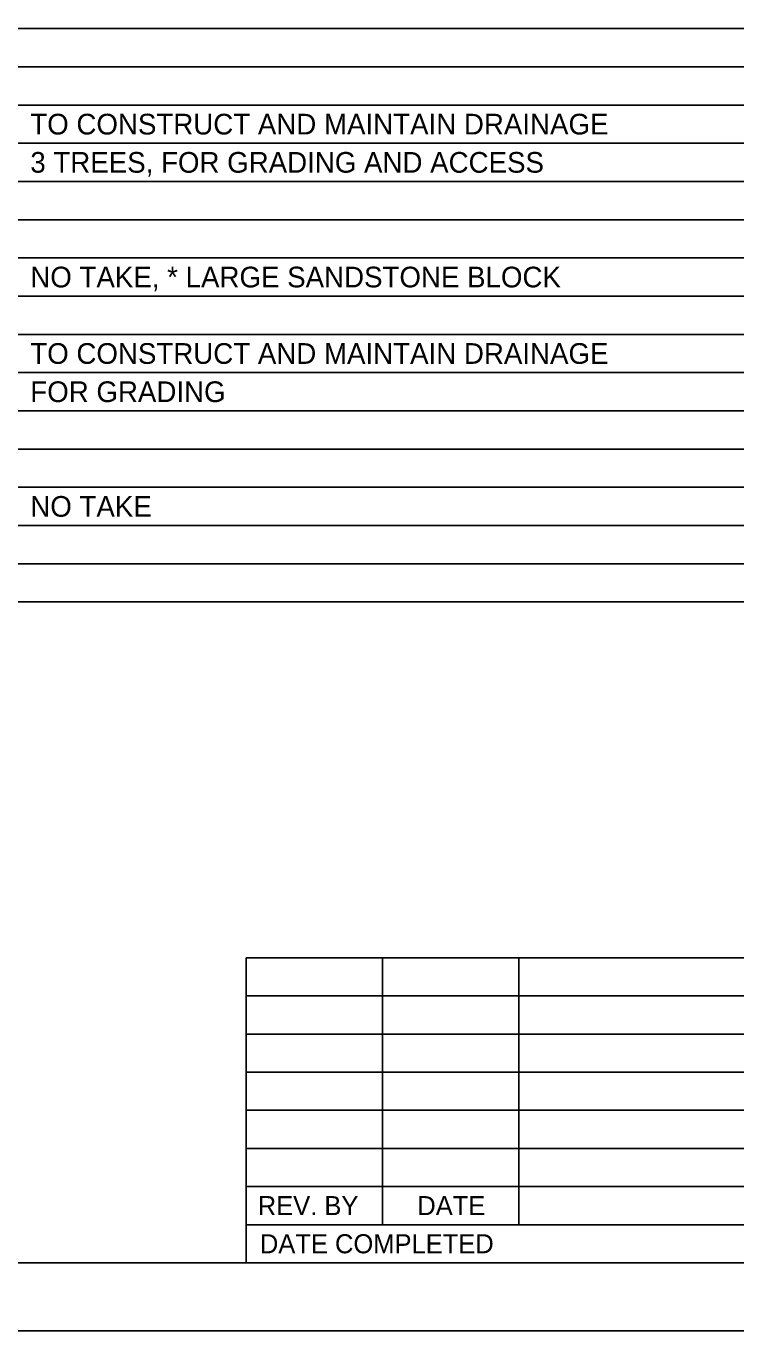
# Model space of a CAD drawing. Extents: x 0 to 34, y 0 to 22.
# Drawn here: x 23.58 to 28.79, y 0 to 9.58 of the extents above; entities that cross this region are included whole.
import ezdxf

# ---------------------------------------------------------------- set-up
doc = ezdxf.new("R2010")
doc.units = 0
for name, color, linetype in [('SH_Border', 7, 'Continuous'), ('SH_Cut_Line', 7, 'Continuous'), ('SH_Text', 7, 'Continuous')]:
    doc.layers.add(name, color=color, linetype=linetype)

msp = doc.modelspace()

# ---------------------------------------------------------------- linework, layer by layer
at = {"layer": 'SH_Border'}
msp.add_lwpolyline([(1.5, 21.5), (33.5, 21.5), (33.5, 0.5), (1.5, 0.5)], close=True, dxfattribs=at)
at = {"layer": 'SH_Cut_Line'}
msp.add_lwpolyline([(0, 0), (34, 0), (34, 22), (0, 22)], close=True, dxfattribs=at)
at = {"layer": 'SH_Text'}
for p, q in [((1.5, 9.5636), (32, 9.5636)), ((1.5, 9.2829), (32, 9.2829)), ((1.5, 9.0022), (32, 9.0022)), ((1.5, 8.7214), (32, 8.7214)), ((1.5, 8.4407), (32, 8.4407)), ((1.5, 8.16), (32, 8.16)), ((1.5, 7.8793), (32, 7.8793)), ((1.5, 7.5985), (32, 7.5985)), ((1.5, 7.3178), (32, 7.3178)), ((1.5, 7.0371), (32, 7.0371)), ((1.5, 6.7564), (32, 6.7564)), ((1.5, 6.4756), (32, 6.4756)), ((1.5, 6.1949), (32, 6.1949)), ((1.5, 5.9142), (32, 5.9142)), ((1.5, 5.6335), (32, 5.6335)), ((32, 5.3527), (1.5, 5.3527)), ((1.5, 5.3527), (32, 5.3527)), ((25.1966, 2.74), (25.1966, 0.5)), ((25.1966, 2.74), (32, 2.74)), ((26.1966, 2.74), (26.1966, 0.78)), ((27.1966, 2.74), (27.1966, 0.78)), ((25.1966, 2.46), (32, 2.46)), ((25.1966, 2.18), (32, 2.18)), ((25.1966, 1.9), (32, 1.9)), ((25.1966, 1.62), (32, 1.62)), ((25.1966, 1.34), (32, 1.34)), ((25.1966, 1.06), (32, 1.06)), ((25.1966, 0.78), (32, 0.78))]:
    msp.add_line(p, q, dxfattribs=at)

# ---------------------------------------------------------------- texts
for s, height, p in [('TO CONSTRUCT AND MAINTAIN DRAINAGE', 0.151922, (23.6113, 8.7858)), ('3 TREES, FOR GRADING AND ACCESS', 0.151922, (23.6113, 8.5051)), ('NO TAKE, * LARGE SANDSTONE BLOCK', 0.151922, (23.6113, 7.6629)), ('TO CONSTRUCT AND MAINTAIN DRAINAGE', 0.151922, (23.6113, 7.1015)), ('FOR GRADING', 0.151922, (23.6113, 6.8208)), ('NO TAKE', 0.15192, (23.6113, 5.9786)), ('REV. BY', 0.14, (25.2808, 0.85)), ('DATE', 0.14, (26.4521, 0.85)), ('DATE COMPLETED', 0.14, (25.2966, 0.57))]:
    msp.add_text(s, height=height, dxfattribs=at).set_placement(p)

doc.saveas('drawing.dxf')
